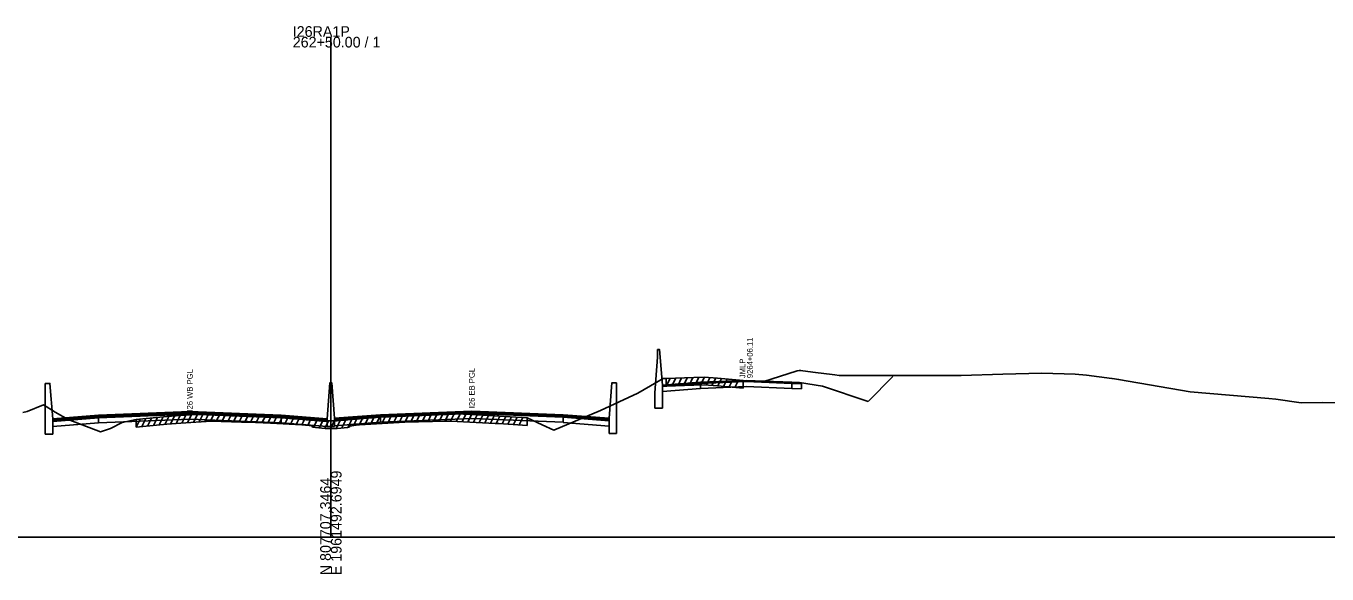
# Model space of a CAD drawing. Extents: x 1017 to 19997, y -1947 to 50737.
# Drawn here: x 10520 to 10861.4, y 12490.3 to 12634.3 of the extents above; entities that cross this region are included whole.
import ezdxf

# ---------------------------------------------------------------- set-up
doc = ezdxf.new("R2010")
doc.units = 0
for name, color, linetype in [('RD_GPK_XS_Cell', 7, 'Continuous'), ('RD_XS_Base', 7, 'Continuous'), ('RD_XS_ExGround', 7, 'Continuous'), ('RD_XS_ExPaveRet', 7, 'Continuous'), ('RD_XS_Greenside', 7, 'Continuous'), ('RD_XS_MedBWall', 7, 'Continuous'), ('RD_XS_Pave', 7, 'Continuous'), ('RD_XS_PaveOvlay', 7, 'Continuous'), ('RD_XS_TieSlope', 7, 'Continuous'), ('RD_XS_TX_Notes', 7, 'Continuous')]:
    doc.layers.add(name, color=color, linetype=linetype)

msp = doc.modelspace()

# ---------------------------------------------------------------- linework, layer by layer
at = {"layer": 'RD_GPK_XS_Cell'}
for p, q in [((10600, 12500), (10600, 12631.44)), ((10000, 12500), (10600, 12500)), ((10600, 12500), (11200, 12500))]:
    msp.add_line(p, q, dxfattribs=at)
at = {"layer": 'RD_XS_Base'}
for points in [[(10697, 12540.4), (10687, 12539.6)], [(10697, 12540.4), (10709, 12540.88), (10721, 12540.4)], [(10697, 12539.06), (10697, 12540.4)], [(10721, 12540.4), (10721, 12539.08)], [(10721, 12540.4), (10723, 12540.32), (10723.5, 12540.3)], [(10687, 12539.6), (10687, 12538.26)], [(10687, 12538.26), (10697, 12539.06)], [(10721, 12539.08), (10709, 12539.54), (10697, 12539.06)], [(10723.5, 12538.96), (10721, 12539.08)], [(10723.5, 12540.3), (10723.5, 12538.96)], [(10539, 12531.34), (10527, 12530.38)], [(10527, 12530.38), (10527, 12529.04)], [(10539, 12530), (10539, 12531.34)], [(10539.05, 12531.34), (10539.05, 12530)], [(10539.05, 12530), (10563, 12530.97), (10587, 12530.01)], [(10587, 12530.01), (10587, 12531.35)], [(10599, 12530.4), (10587, 12531.35)], [(10599, 12529.06), (10599, 12530.4)], [(10601, 12529.21), (10601, 12530.55)], [(10613, 12530.16), (10601, 12529.21)], [(10613, 12530.16), (10613, 12531.5)], [(10660.95, 12530.16), (10637, 12531.12), (10613, 12530.16)], [(10660.95, 12530.16), (10660.95, 12531.5)], [(10661, 12530.16), (10660.95, 12530.16)], [(10661, 12531.5), (10661, 12530.16)], [(10661, 12531.49), (10673, 12530.53)], [(10661, 12530.15), (10661, 12531.49)], [(10673, 12529.19), (10661, 12530.15)], [(10673, 12530.53), (10673, 12529.19)], [(10527, 12529.04), (10539, 12530)], [(10539.05, 12530), (10539, 12530)], [(10587, 12530.01), (10599, 12529.06)]]:
    msp.add_lwpolyline(points, dxfattribs=at)
at = {"layer": 'RD_XS_ExGround'}
msp.add_lwpolyline([(10519.14, 12532.7), (10520.28, 12532.96), (10524.57, 12534.73), (10527.61, 12532.8), (10531.04, 12530.88), (10539.59, 12527.7), (10542.13, 12528.55), (10545.2, 12530.08), (10548.92, 12530.91), (10550.62, 12531.06), (10556.99, 12531.68), (10560.6, 12531.94), (10568.55, 12532.5), (10576.56, 12532.24), (10580.25, 12532.11), (10584.12, 12531.94), (10592.4, 12531.52), (10594.34, 12531.31), (10595.05, 12531.22), (10595.2, 12530.87), (10595.98, 12530.79), (10598.48, 12530.52), (10600, 12530.52), (10601.34, 12530.53), (10601.65, 12530.55), (10604.42, 12530.83), (10604.81, 12530.9), (10604.97, 12531.19), (10607.16, 12531.46), (10607.51, 12531.5), (10608.99, 12531.58), (10619.38, 12532.2), (10630.23, 12532.42), (10631.51, 12532.45), (10643.1, 12531.87), (10644.06, 12531.82), (10651.5, 12531.36), (10655.44, 12529.5), (10658.52, 12528.1), (10670.79, 12533.29), (10680.52, 12537.79), (10687.2, 12541.67), (10688.02, 12541.68), (10695.27, 12541.91), (10697.93, 12542), (10701.46, 12541.74), (10708.19, 12541.16), (10712.31, 12540.79), (10713.4, 12540.79), (10722.34, 12543.66), (10722.92, 12543.81), (10723.32, 12543.78), (10723.83, 12543.71), (10727.15, 12543.28), (10731.55, 12542.72), (10732.25, 12542.63), (10733.37, 12542.49), (10740.98, 12542.43), (10765.45, 12542.46), (10776.36, 12542.79), (10786.59, 12543.05), (10795.34, 12542.85), (10798.32, 12542.54), (10804.99, 12541.71), (10805.63, 12541.6), (10806.73, 12541.43), (10825.51, 12538.2), (10846.13, 12536.41), (10847.98, 12536.22), (10854.63, 12535.24), (10860.35, 12535.33), (10876.54, 12534.98)], dxfattribs=at)
at = {"layer": 'RD_XS_ExPaveRet'}
for p, q in [((10688.02, 12539.68), (10689.04, 12541.71)), ((10688.02, 12539.68), (10688.02, 12541.68)), ((10689.52, 12539.73), (10690.54, 12541.76)), ((10691.02, 12539.77), (10692.04, 12541.81)), ((10692.52, 12539.82), (10693.54, 12541.85)), ((10694.02, 12539.87), (10695.04, 12541.9)), ((10695.52, 12539.92), (10696.54, 12541.95)), ((10697.02, 12539.97), (10698.04, 12541.99)), ((10698.52, 12539.95), (10699.49, 12541.88)), ((10700.02, 12539.84), (10700.99, 12541.77)), ((10701.52, 12539.73), (10702.48, 12541.65)), ((10703.02, 12539.6), (10703.98, 12541.52)), ((10704.52, 12539.48), (10705.48, 12541.39)), ((10706.02, 12539.35), (10706.98, 12541.27)), ((10708.19, 12541.16), (10708.19, 12539.16)), ((10688.02, 12539.68), (10695.27, 12539.91)), ((10695.27, 12539.91), (10697.93, 12540)), ((10697.93, 12540), (10701.46, 12539.74)), ((10701.46, 12539.74), (10708.19, 12539.16)), ((10548.92, 12528.91), (10549.97, 12531)), ((10548.92, 12528.91), (10548.92, 12530.91)), ((10550.42, 12529.04), (10551.47, 12531.14)), ((10551.92, 12529.19), (10552.97, 12531.29)), ((10553.42, 12529.33), (10554.47, 12531.43)), ((10554.92, 12529.48), (10555.97, 12531.58)), ((10556.42, 12529.62), (10557.47, 12531.71)), ((10557.92, 12529.74), (10558.96, 12531.82)), ((10559.42, 12529.85), (10560.46, 12531.93)), ((10560.6, 12529.94), (10568.55, 12530.5)), ((10560.92, 12529.96), (10561.96, 12532.04)), ((10562.42, 12530.07), (10563.46, 12532.14)), ((10563.92, 12530.17), (10564.96, 12532.25)), ((10565.42, 12530.28), (10566.46, 12532.35)), ((10566.92, 12530.38), (10567.96, 12532.46)), ((10568.42, 12530.49), (10569.41, 12532.47)), ((10568.55, 12530.5), (10576.56, 12530.24)), ((10569.92, 12530.46), (10570.91, 12532.42)), ((10571.42, 12530.41), (10572.41, 12532.38)), ((10572.92, 12530.36), (10573.91, 12532.33)), ((10574.42, 12530.31), (10575.41, 12532.28)), ((10575.92, 12530.26), (10576.9, 12532.23)), ((10576.56, 12530.24), (10580.25, 12530.11)), ((10577.42, 12530.21), (10578.4, 12532.18)), ((10578.92, 12530.16), (10579.9, 12532.12)), ((10580.25, 12530.11), (10584.12, 12529.94)), ((10580.42, 12530.1), (10581.4, 12532.06)), ((10581.92, 12530.04), (10582.9, 12531.99)), ((10583.42, 12529.97), (10584.4, 12531.92)), ((10584.92, 12529.9), (10585.9, 12531.85)), ((10586.42, 12529.82), (10587.4, 12531.77)), ((10587.92, 12529.75), (10588.9, 12531.7)), ((10589.42, 12529.67), (10590.4, 12531.62)), ((10590.92, 12529.59), (10591.9, 12531.55)), ((10592.42, 12529.52), (10593.37, 12531.41)), ((10593.92, 12529.35), (10594.87, 12531.24)), ((10595.42, 12528.85), (10596.37, 12530.75)), ((10596.92, 12528.69), (10597.87, 12530.58)), ((10598.42, 12528.52), (10599.42, 12530.52)), ((10599.92, 12528.52), (10600.92, 12530.52)), ((10601.42, 12528.53), (10602.47, 12530.63)), ((10602.92, 12528.68), (10603.97, 12530.78)), ((10604.42, 12528.83), (10605.64, 12531.27)), ((10605.92, 12529.31), (10606.99, 12531.44)), ((10607.42, 12529.49), (10608.45, 12531.55)), ((10608.92, 12529.58), (10609.95, 12531.64)), ((10608.99, 12529.58), (10619.38, 12530.2)), ((10610.42, 12529.67), (10611.45, 12531.73)), ((10611.92, 12529.76), (10612.95, 12531.82)), ((10613.42, 12529.85), (10614.45, 12531.91)), ((10614.92, 12529.94), (10615.95, 12532)), ((10616.42, 12530.03), (10617.45, 12532.09)), ((10617.92, 12530.12), (10618.95, 12532.18)), ((10619.38, 12530.2), (10630.23, 12530.42)), ((10619.42, 12530.2), (10620.43, 12532.22)), ((10620.92, 12530.23), (10621.93, 12532.25)), ((10622.42, 12530.26), (10623.43, 12532.28)), ((10623.92, 12530.29), (10624.93, 12532.32)), ((10625.42, 12530.33), (10626.43, 12532.35)), ((10626.92, 12530.36), (10627.93, 12532.38)), ((10628.42, 12530.39), (10629.43, 12532.41)), ((10629.92, 12530.42), (10630.93, 12532.44)), ((10630.23, 12530.42), (10631.51, 12530.45)), ((10631.42, 12530.45), (10632.4, 12532.41)), ((10631.51, 12530.45), (10643.1, 12529.87)), ((10632.92, 12530.38), (10633.9, 12532.33)), ((10634.42, 12530.31), (10635.4, 12532.26)), ((10635.92, 12530.23), (10636.9, 12532.18)), ((10637.42, 12530.16), (10638.4, 12532.11)), ((10638.92, 12530.08), (10639.9, 12532.03)), ((10640.42, 12530), (10641.4, 12531.95)), ((10641.92, 12529.93), (10642.9, 12531.88)), ((10643.42, 12529.85), (10644.39, 12531.8)), ((10644.92, 12529.76), (10645.89, 12531.7)), ((10646.42, 12529.67), (10647.39, 12531.61)), ((10647.92, 12529.58), (10648.89, 12531.52)), ((10649.42, 12529.49), (10650.39, 12531.43)), ((10651.5, 12531.36), (10651.5, 12529.36)), ((10548.92, 12528.91), (10550.62, 12529.06)), ((10550.62, 12529.06), (10556.99, 12529.68)), ((10556.99, 12529.68), (10560.6, 12529.94)), ((10584.12, 12529.94), (10592.4, 12529.52)), ((10592.4, 12529.52), (10594.34, 12529.31)), ((10594.34, 12529.31), (10595.05, 12529.22)), ((10595.05, 12529.22), (10595.2, 12528.87)), ((10595.2, 12528.87), (10595.98, 12528.79)), ((10595.98, 12528.79), (10598.48, 12528.52)), ((10598.48, 12528.52), (10600, 12528.52)), ((10600, 12528.52), (10601.34, 12528.53)), ((10601.34, 12528.53), (10601.65, 12528.55)), ((10601.65, 12528.55), (10604.42, 12528.83)), ((10604.42, 12528.83), (10604.81, 12528.9)), ((10604.81, 12528.9), (10604.97, 12529.19)), ((10604.97, 12529.19), (10607.16, 12529.46)), ((10607.16, 12529.46), (10607.51, 12529.5)), ((10607.51, 12529.5), (10608.99, 12529.58)), ((10643.1, 12529.87), (10644.06, 12529.82)), ((10644.06, 12529.82), (10651.5, 12529.36))]:
    msp.add_line(p, q, dxfattribs=at)
at = {"layer": 'RD_XS_Greenside'}
for points in [[(10723, 12540.63), (10729, 12539.67)], [(10729, 12539.67), (10741, 12535.67)]]:
    msp.add_lwpolyline(points, dxfattribs=at)
at = {"layer": 'RD_XS_MedBWall'}
for points in [[(10685.75, 12547.25), (10685, 12537.91)], [(10687, 12539.91), (10686.25, 12549.25), (10685.75, 12549.25)], [(10685.75, 12549.25), (10685.75, 12547.25)], [(10527, 12531.06), (10526.25, 12540.4), (10525, 12540.4)], [(10525, 12540.4), (10525, 12527.06)], [(10599, 12531.06), (10599.75, 12540.55), (10600.25, 12540.55), (10601, 12531.21)], [(10673, 12531.21), (10673.75, 12540.55), (10675, 12540.55)], [(10675, 12540.55), (10675, 12527.21)], [(10685, 12537.91), (10685, 12533.91)], [(10687, 12533.91), (10687, 12539.91)], [(10685, 12533.91), (10687, 12533.91)], [(10527, 12527.06), (10527, 12531.06)], [(10599, 12529.06), (10599, 12531.06)], [(10601, 12531.21), (10601, 12529.06)], [(10673, 12527.21), (10673, 12531.21)], [(10525, 12527.06), (10527, 12527.06)], [(10601, 12529.06), (10599, 12529.06)], [(10675, 12527.21), (10673, 12527.21)]]:
    msp.add_lwpolyline(points, dxfattribs=at)
at = {"layer": 'RD_XS_Pave'}
for points in [[(10539, 12531.68), (10527, 12530.72)], [(10527, 12530.72), (10527, 12530.38)], [(10539, 12531.34), (10539, 12531.68)], [(10539.05, 12531.34), (10539, 12531.34)], [(10539.05, 12531.68), (10563, 12532.65), (10587, 12531.69)], [(10587, 12531.35), (10563, 12532.31), (10539.05, 12531.34)], [(10539.05, 12531.34), (10539.05, 12531.68)], [(10587, 12531.69), (10587, 12531.35)], [(10587, 12531.69), (10599, 12530.74)], [(10599, 12530.74), (10599, 12530.4)], [(10613, 12531.84), (10601, 12530.89)], [(10601, 12530.55), (10613, 12531.5)], [(10601, 12530.89), (10601, 12530.55)], [(10660.95, 12531.84), (10637, 12532.8), (10613, 12531.84)], [(10613, 12531.5), (10637, 12532.46), (10660.95, 12531.5)], [(10613, 12531.84), (10613, 12531.5)], [(10660.95, 12531.5), (10660.95, 12531.84)], [(10660.95, 12531.84), (10661, 12531.84)], [(10661, 12531.5), (10660.95, 12531.5)], [(10661, 12531.84), (10661, 12531.5)], [(10661, 12531.49), (10661, 12531.83)], [(10673, 12530.87), (10673, 12530.53)]]:
    msp.add_lwpolyline(points, dxfattribs=at)
at = {"layer": 'RD_XS_PaveOvlay'}
for points in [[(10697, 12540.71), (10687, 12539.91)], [(10687, 12539.6), (10697, 12540.4)], [(10697, 12540.71), (10709, 12541.19), (10721, 12540.71)], [(10721, 12540.4), (10709, 12540.88), (10697, 12540.4)], [(10697, 12540.4), (10697, 12540.71)], [(10721, 12540.71), (10721, 12540.4)], [(10721, 12540.71), (10723, 12540.63)], [(10723, 12540.32), (10721, 12540.4)], [(10723, 12540.63), (10723, 12540.32)], [(10687, 12539.91), (10687, 12539.6)], [(10539, 12532.02), (10527, 12531.06)], [(10527, 12531.06), (10527, 12530.72)], [(10539.05, 12532.02), (10539, 12532.02)], [(10539, 12532.02), (10539, 12531.68)], [(10539, 12531.68), (10539.05, 12531.68)], [(10539.05, 12532.02), (10563, 12532.98), (10587, 12532.02)], [(10539.05, 12531.68), (10539.05, 12532.02)], [(10587, 12532.02), (10587, 12531.69)], [(10587, 12532.02), (10599, 12531.06)], [(10599, 12531.06), (10599, 12530.74)], [(10613, 12532.17), (10601, 12531.21)], [(10601, 12531.21), (10601, 12530.89)], [(10660.95, 12532.17), (10637, 12533.13), (10613, 12532.17)], [(10613, 12532.17), (10613, 12531.84)], [(10660.95, 12531.84), (10660.95, 12532.17)], [(10660.95, 12532.17), (10661, 12532.17)], [(10661, 12532.17), (10661, 12531.84)], [(10661, 12532.17), (10673, 12531.21)], [(10661, 12531.83), (10661, 12532.17)], [(10673, 12530.87), (10661, 12531.83)], [(10673, 12531.21), (10673, 12530.87)]]:
    msp.add_lwpolyline(points, dxfattribs=at)
at = {"layer": 'RD_XS_TieSlope'}
msp.add_lwpolyline([(10741, 12535.67), (10747.51, 12542.18)], dxfattribs=at)

# ---------------------------------------------------------------- texts
at = {"layer": 'RD_GPK_XS_Cell'}
for s, p in [('I26RA1P', (10590, 12631.44)), ('262+50.00 / 1', (10590, 12628.64))]:
    msp.add_text(s, height=2.8, dxfattribs=at).set_placement(p)
for s, p in [('E 1961492.6949', (10602.8, 12490)), ('N 807707.3464', (10600, 12490))]:
    msp.add_text(s, height=2.8, rotation=90, dxfattribs=at).set_placement(p)
at = {"layer": 'RD_XS_TX_Notes'}
for s, p in [(' 9264+06.11', (10710.73, 12541.21)), ('I26 WB PGL', (10563.75, 12532.98)), ('I26 EB PGL', (10637.75, 12533.86)), (' JMLP', (10708.77, 12541.21))]:
    msp.add_text(s, height=1.5, rotation=90, dxfattribs=at).set_placement(p)

doc.saveas('drawing.dxf')
